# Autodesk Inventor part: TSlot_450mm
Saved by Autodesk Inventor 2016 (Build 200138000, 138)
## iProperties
Created: 2016-03
Part Number: TSlot_450mm
Material: Generic
Document SubType Name: Modeling
Designer: bongo_000
Density: 1 g/cm^3
Appearance: Default
Author: bongo_000
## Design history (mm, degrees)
feature "SOLID1"
body "Solid1"
